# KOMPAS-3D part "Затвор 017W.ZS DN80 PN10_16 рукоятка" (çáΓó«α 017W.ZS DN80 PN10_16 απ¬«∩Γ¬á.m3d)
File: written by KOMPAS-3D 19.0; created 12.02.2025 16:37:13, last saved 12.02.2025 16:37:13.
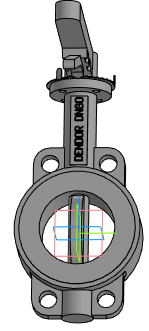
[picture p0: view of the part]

Document properties: Автор: Евгений; Полное имя файла: Затвор 017W.ZS DN80 PN10_16 рукоятка.a3d

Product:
- Part/product: Затвор 017W.ZS DN80 PN10_16 рукоятка
    Масса: 6.36807

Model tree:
1. Операция без истории:1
